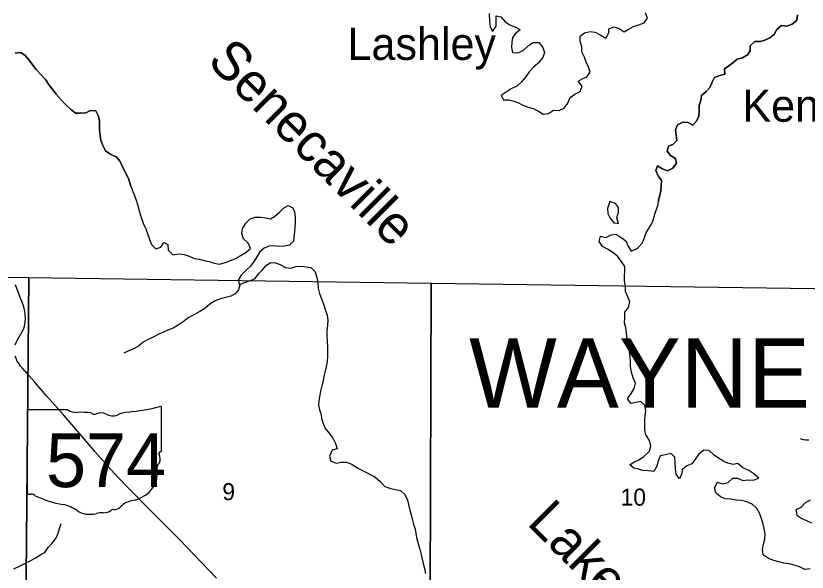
# Model space of a CAD drawing. Extents: x 0 to 191, y 0 to 55.
# Drawn here: x 144.524 to 145.495, y 22.998 to 23.68 of the extents above; entities that cross this region are included whole.
import ezdxf

# ---------------------------------------------------------------- set-up
doc = ezdxf.new("R2010")
doc.units = 0
for name, color, linetype in [('GM_X_Corporation', 7, 'Continuous'), ('GM_X_Major_Lake', 7, 'Continuous'), ('GM_X_Major_Lake_Text', 7, 'Continuous'), ('GM_X_Minor_River', 7, 'Continuous'), ('GM_X_Section_Text', 7, 'Continuous'), ('GM_X_State_Location', 7, 'Continuous'), ('GM_X_State_Route', 7, 'Continuous'), ('GM_X_State_Shield', 7, 'Continuous'), ('GM_X_Township_Road', 7, 'Continuous'), ('GM_X_Township_Text', 7, 'Continuous'), ('GM_X_Unincorporated_Text', 7, 'Continuous')]:
    doc.layers.add(name, color=color, linetype=linetype)

msp = doc.modelspace()

# ---------------------------------------------------------------- linework, layer by layer
at = {"layer": 'GM_X_Corporation'}
for points in [[(144.54037, 23.35908), (144.5357, 22.85387), (144.03613, 22.86315), (144.04141, 23.36476)], [(145.03385, 23.35238), (145.03203, 22.84664), (144.5357, 22.85387), (144.54037, 23.35908)], [(145.53282, 23.34555), (145.53082, 22.83943), (145.03203, 22.84664), (145.03385, 23.35238)]]:
    msp.add_lwpolyline(points, close=True, dxfattribs=at)
at = {"layer": 'GM_X_Major_Lake'}
for points in [[(145.1046, 23.68315), (145.10503, 23.67367), (145.10602, 23.66703), (145.1087, 23.66098), (145.11339, 23.66746), (145.11336, 23.67353), (145.11351, 23.68017), (145.119, 23.67906), (145.12434, 23.67284), (145.13004, 23.66927), (145.13687, 23.66628), (145.14294, 23.6631), (145.13748, 23.6587), (145.13354, 23.65355), (145.13262, 23.64786), (145.13228, 23.6414), (145.13346, 23.63515), (145.14008, 23.63463), (145.14631, 23.6377), (145.1529, 23.64362), (145.15893, 23.64745), (145.16575, 23.64731), (145.17051, 23.64146), (145.17244, 23.63521), (145.17059, 23.62894), (145.16476, 23.62208), (145.15911, 23.61711), (145.15366, 23.61138), (145.14916, 23.60472), (145.14446, 23.599), (145.13862, 23.59403), (145.13183, 23.59057), (145.1258, 23.58655), (145.11958, 23.58234), (145.12244, 23.57724), (145.12907, 23.5769), (145.13381, 23.57598), (145.13988, 23.57374), (145.14595, 23.57056), (145.15259, 23.56813), (145.15885, 23.56628), (145.16511, 23.56328), (145.17119, 23.55934), (145.17762, 23.56033), (145.18365, 23.56435), (145.19046, 23.56401), (145.19669, 23.56671), (145.2012, 23.57299), (145.204, 23.57984), (145.20984, 23.58386), (145.21625, 23.5875), (145.21868, 23.59378), (145.2141, 23.60001), (145.21957, 23.60346), (145.22447, 23.60538), (145.2286, 23.61091), (145.22667, 23.61735), (145.2238, 23.62321)], [(145.2238, 23.62321), (145.22149, 23.62945), (145.21842, 23.63607), (145.21858, 23.64252), (145.21627, 23.64877), (145.21642, 23.65503), (145.22169, 23.65942), (145.2285, 23.66098), (145.23456, 23.65988), (145.24082, 23.6567), (145.24766, 23.65276), (145.2516, 23.65923), (145.25138, 23.66397), (145.25799, 23.66667), (145.26405, 23.66462), (145.27051, 23.66068), (145.27655, 23.66413), (145.28183, 23.6672), (145.28825, 23.66914), (145.29486, 23.67164), (145.29899, 23.67717), (145.29668, 23.68361)], [(145.2874, 23.39603), (145.29286, 23.40175), (145.29509, 23.40821), (145.29695, 23.41335), (145.29957, 23.4181), (145.3037, 23.42477), (145.30575, 23.42952), (145.30798, 23.43693), (145.31188, 23.4489), (145.31242, 23.45384), (145.31372, 23.45897), (145.31519, 23.46523), (145.31572, 23.4715), (145.31606, 23.47814), (145.31187, 23.48399), (145.30899, 23.49042), (145.31123, 23.49631), (145.3173, 23.49256), (145.32356, 23.49013), (145.33017, 23.4934), (145.33467, 23.49931), (145.33313, 23.50518), (145.32705, 23.50874), (145.32304, 23.51403), (145.32452, 23.52029), (145.33019, 23.52241), (145.3347, 23.52737), (145.3339, 23.53382), (145.3333, 23.54026), (145.33591, 23.54654), (145.34214, 23.54961), (145.34876, 23.54927), (145.35465, 23.5459), (145.35916, 23.55086), (145.36177, 23.55713), (145.36212, 23.5632), (145.36246, 23.56984), (145.3645, 23.57649), (145.36522, 23.58238), (145.37106, 23.58735), (145.37538, 23.59212), (145.37837, 23.59858), (145.38118, 23.60448), (145.3876, 23.60699), (145.39364, 23.60873), (145.39342, 23.61518), (145.3985, 23.61863), (145.40359, 23.62264), (145.40886, 23.62704), (145.41529, 23.62878), (145.42151, 23.63224), (145.42489, 23.63719), (145.42485, 23.64345), (145.43069, 23.64861), (145.43731, 23.64865), (145.44279, 23.65039), (145.44902, 23.65309), (145.45411, 23.6571), (145.45748, 23.66338), (145.46312, 23.66835), (145.46994, 23.66725), (145.47636, 23.66976), (145.4822, 23.67435), (145.48292, 23.68118)], [(145.48292, 23.68118), (145.4822, 23.67435), (145.47636, 23.66976), (145.46994, 23.66725), (145.46312, 23.66835), (145.45748, 23.66338), (145.45411, 23.6571), (145.44902, 23.65309), (145.44279, 23.65039), (145.43731, 23.64865), (145.43069, 23.64861), (145.42485, 23.64345), (145.42489, 23.63719), (145.42151, 23.63224), (145.41529, 23.62878), (145.40886, 23.62704), (145.40359, 23.62264), (145.3985, 23.61863), (145.39342, 23.61518), (145.39364, 23.60873), (145.3876, 23.60699), (145.38118, 23.60448), (145.37837, 23.59858), (145.37538, 23.59212), (145.37106, 23.58735), (145.36522, 23.58238), (145.3645, 23.57649), (145.36246, 23.56984), (145.36212, 23.5632), (145.36177, 23.55713), (145.35916, 23.55086), (145.35465, 23.5459), (145.34876, 23.54927), (145.34214, 23.54961), (145.33591, 23.54654), (145.3333, 23.54026), (145.3339, 23.53382), (145.3347, 23.52737), (145.33019, 23.52241), (145.32452, 23.52029), (145.32304, 23.51403), (145.32705, 23.50874), (145.33313, 23.50518), (145.33467, 23.49931), (145.33017, 23.4934), (145.32356, 23.49013), (145.3173, 23.49256), (145.31123, 23.49631), (145.30899, 23.49042), (145.31187, 23.48399), (145.31606, 23.47814), (145.31572, 23.4715), (145.31519, 23.46523), (145.31372, 23.45897), (145.31242, 23.45384), (145.31224, 23.45219)], [(144.66622, 23.46937), (144.66468, 23.4736), (144.66256, 23.48061), (144.65567, 23.49422), (144.65222, 23.5014), (144.64726, 23.50706), (144.64081, 23.51024), (144.63454, 23.51476), (144.6309, 23.52099), (144.6286, 23.52724), (144.62761, 23.5333), (144.62682, 23.53974), (144.62679, 23.54448), (144.62694, 23.55074), (144.62558, 23.55718), (144.62251, 23.56342), (144.61589, 23.56414), (144.61022, 23.56126), (144.60379, 23.56084), (144.59755, 23.5608), (144.59127, 23.5655), (144.58518, 23.57134), (144.58004, 23.57718), (144.57375, 23.58397), (144.57013, 23.58888), (144.56517, 23.59492), (144.56078, 23.60191), (144.55544, 23.60794), (144.54935, 23.61416), (144.54019, 23.62624), (144.53543, 23.6319), (144.52992, 23.63509), (144.52349, 23.63429)], [(144.52349, 23.63429), (144.52992, 23.63509), (144.53543, 23.6319), (144.54019, 23.62624), (144.54935, 23.61416), (144.55544, 23.60794), (144.56078, 23.60191), (144.56517, 23.59492), (144.57013, 23.58888), (144.57375, 23.58397), (144.58004, 23.57718), (144.58518, 23.57134), (144.59127, 23.5655), (144.59755, 23.5608), (144.60379, 23.56084), (144.61022, 23.56126), (144.61589, 23.56414), (144.62251, 23.56342), (144.62558, 23.55718), (144.62694, 23.55074), (144.62679, 23.54448), (144.62682, 23.53974), (144.62761, 23.5333), (144.6286, 23.52724), (144.6309, 23.52099), (144.63454, 23.51476), (144.64081, 23.51024), (144.64726, 23.50706), (144.65222, 23.5014), (144.65567, 23.49422), (144.66256, 23.48061), (144.66468, 23.4736), (144.66757, 23.46566), (144.66988, 23.4596), (144.67238, 23.45279), (144.6745, 23.44598), (144.67605, 23.43992), (144.67798, 23.43291), (144.68067, 23.42591), (144.68374, 23.41892), (144.68586, 23.41305), (144.68836, 23.40586), (144.69105, 23.39943), (144.696, 23.39453), (144.70223, 23.39628), (144.70599, 23.40199), (144.71073, 23.39956), (144.71115, 23.39273), (144.71705, 23.38708)], [(144.71705, 23.38708), (144.72424, 23.38807), (144.73067, 23.38755), (144.73712, 23.3855), (144.74301, 23.38251), (144.74907, 23.3816), (144.75532, 23.38012), (144.76157, 23.37883), (144.76764, 23.37697), (144.77427, 23.37569), (144.78089, 23.37744), (144.78693, 23.37956), (144.79354, 23.38264), (144.80033, 23.38629), (144.80674, 23.39031), (144.8122, 23.39471), (144.80913, 23.40151), (144.80361, 23.4066), (144.8015, 23.41304), (144.80222, 23.4193), (144.80653, 23.42577), (144.8118, 23.43131), (144.81803, 23.43324), (144.82447, 23.4331), (144.83053, 23.43238), (144.83659, 23.43128), (144.84149, 23.43396), (144.84771, 23.4395), (144.85241, 23.44446), (144.85844, 23.44773), (144.86395, 23.44473), (144.86606, 23.43962), (144.86705, 23.43356), (144.86689, 23.4273), (144.86655, 23.42104), (144.86602, 23.41478), (144.86511, 23.40851), (144.86495, 23.40377), (144.85987, 23.3988), (144.85401, 23.39782), (144.84739, 23.3974), (144.84095, 23.39812), (144.83471, 23.39751), (144.82885, 23.39519), (144.82339, 23.39061), (144.82002, 23.38471), (144.81683, 23.37937), (144.81214, 23.37328), (144.8063, 23.36774), (144.80066, 23.3622), (144.79691, 23.35592), (144.79883, 23.35062), (144.80525, 23.35313), (144.81205, 23.35564), (144.81791, 23.35814), (144.82185, 23.36386), (144.82693, 23.36863), (144.83125, 23.37378), (144.83653, 23.3776), (144.84278, 23.37708), (144.84847, 23.37503), (144.85511, 23.37147), (144.86174, 23.37056), (144.86759, 23.37287), (144.87421, 23.37329), (144.88028, 23.37238), (144.88596, 23.37147), (144.89129, 23.3662), (144.8936, 23.35919), (144.89459, 23.35256), (144.89519, 23.34612), (144.89655, 23.33968), (144.89924, 23.33306), (144.90174, 23.32644), (144.90367, 23.31981), (144.90617, 23.313), (144.90696, 23.30713), (144.90662, 23.30068), (144.90591, 23.29384), (144.90576, 23.28721), (144.90617, 23.28095), (144.9064, 23.27431), (144.90662, 23.26863), (144.90647, 23.26275), (144.90594, 23.25611), (144.90484, 23.24965), (144.90337, 23.24262), (144.90226, 23.23788), (144.90116, 23.23237), (144.89968, 23.22629), (144.89783, 23.21983), (144.89673, 23.213), (144.896, 23.20787), (144.89565, 23.20313), (144.89682, 23.19707), (144.89875, 23.1912), (144.89916, 23.18646), (144.90109, 23.18022), (144.90358, 23.17417), (144.90854, 23.16832), (144.91293, 23.16209)], [(145.25278, 23.45228), (145.2498, 23.44373), (145.25021, 23.43766), (145.25327, 23.43199), (145.25747, 23.42633), (145.2587, 23.42618)], [(145.2587, 23.42618), (145.26353, 23.4256), (145.26122, 23.43261), (145.26327, 23.43926), (145.26323, 23.44513), (145.25961, 23.45004), (145.25278, 23.45228)], [(145.38091, 23.10154), (145.38484, 23.1082), (145.39129, 23.10635), (145.39772, 23.10771), (145.40336, 23.11306), (145.40942, 23.11329), (145.41568, 23.11048), (145.42192, 23.11109), (145.42836, 23.11056), (145.43534, 23.11326), (145.42926, 23.11853), (145.42299, 23.12248), (145.41578, 23.12603), (145.4095, 23.13111), (145.40383, 23.12994), (145.39739, 23.13142), (145.39264, 23.13347), (145.38619, 23.1376), (145.38067, 23.14155), (145.37459, 23.14701), (145.36815, 23.14735), (145.36156, 23.14238), (145.35311, 23.13095), (145.34707, 23.12825), (145.34142, 23.12347), (145.34107, 23.11873), (145.33808, 23.11245), (145.33407, 23.11812), (145.33346, 23.12475), (145.33304, 23.13158), (145.33262, 23.13878), (145.32786, 23.14349), (145.32106, 23.14174), (145.31445, 23.14056), (145.31221, 23.1341), (145.31035, 23.12802), (145.3068, 23.12136), (145.29998, 23.12226), (145.29335, 23.12279), (145.28672, 23.12446), (145.28198, 23.12556), (145.27723, 23.12951), (145.28269, 23.13315), (145.2876, 23.13508), (145.29439, 23.13986), (145.30135, 23.14636), (145.30321, 23.15263), (145.30128, 23.15944), (145.29707, 23.16624), (145.29553, 23.17192), (145.29568, 23.17875), (145.29583, 23.18501), (145.29618, 23.18975), (145.29671, 23.1962), (145.29554, 23.20264), (145.29078, 23.20735), (145.28454, 23.20599), (145.27906, 23.20462), (145.27449, 23.21028), (145.2788, 23.21695), (145.28274, 23.22323), (145.2844, 23.2295), (145.28115, 23.23631), (145.27921, 23.24331), (145.27823, 23.24994), (145.278, 23.25582), (145.27778, 23.26246), (145.27698, 23.26871), (145.27733, 23.27364), (145.27938, 23.2801), (145.27386, 23.28424), (145.27326, 23.29106), (145.27227, 23.2975), (145.27091, 23.30375), (145.27106, 23.3102), (145.27102, 23.31665), (145.27572, 23.32256), (145.27719, 23.3294), (145.2747, 23.33564), (145.27201, 23.34207), (145.27178, 23.34852), (145.2708, 23.35496), (145.27076, 23.3616), (145.27111, 23.36634), (145.27107, 23.3726), (145.26668, 23.37921), (145.2621, 23.38524), (145.2564, 23.38976), (145.24994, 23.39389), (145.24368, 23.39708), (145.23948, 23.4035), (145.24133, 23.40996), (145.24778, 23.40848), (145.25419, 23.41137), (145.26043, 23.41235), (145.26651, 23.40841), (145.27221, 23.40408), (145.27528, 23.39766), (145.2791, 23.39161), (145.28533, 23.39431), (145.2874, 23.39603)], [(144.91293, 23.16209), (144.91656, 23.15585), (144.91849, 23.14923), (144.91244, 23.14748), (144.90889, 23.14025), (144.91082, 23.13401), (144.91746, 23.13177), (144.92351, 23.13276), (144.92994, 23.13261), (144.9362, 23.13019), (144.94285, 23.12587), (144.94778, 23.12343), (144.95424, 23.12006), (144.95974, 23.11725), (144.96468, 23.11463), (144.97133, 23.10917), (144.97705, 23.10314), (144.98425, 23.10053), (144.98937, 23.09924), (144.996, 23.09795), (145.00133, 23.09324), (145.00478, 23.08606), (145.00576, 23.08076), (145.00711, 23.07545), (145.01021, 23.06334), (145.01214, 23.0569), (145.01388, 23.05046), (145.01504, 23.04554), (145.01622, 23.03891), (145.01815, 23.03153), (145.01989, 23.02623), (145.02125, 23.0196), (145.02261, 23.01373), (145.02416, 23.0071), (145.0259, 23.00086), (145.02688, 22.99612)], [(145.49844, 23.00216), (145.49182, 23.00136), (145.48537, 23.00454), (145.47892, 23.00639), (145.47248, 23.00806), (145.46604, 23.00897), (145.45998, 23.01045), (145.45391, 23.01211), (145.44746, 23.01473), (145.44081, 23.01905), (145.43983, 23.02587), (145.4413, 23.03213), (145.44297, 23.03821), (145.44312, 23.04504), (145.44214, 23.05129), (145.44078, 23.05697), (145.43866, 23.06322), (145.43655, 23.06927), (145.4331, 23.07608), (145.4272, 23.08135), (145.42056, 23.08434), (145.41412, 23.08601), (145.40749, 23.08635), (145.40105, 23.08725), (145.39405, 23.08797), (145.38836, 23.09021), (145.38265, 23.09529), (145.38091, 23.10154)], [(145.49833, 23.08617), (145.49173, 23.08252), (145.48684, 23.07737), (145.48061, 23.0743), (145.48216, 23.06767), (145.48805, 23.06372), (145.49374, 23.06129), (145.50001, 23.05849)]]:
    msp.add_lwpolyline(points, dxfattribs=at)
at = {"layer": 'GM_X_Minor_River'}
for points in [[(144.79952, 23.35089), (144.79722, 23.34419), (144.79327, 23.33924), (144.78817, 23.33656), (144.78155, 23.33481), (144.77531, 23.33326), (144.7687, 23.33056), (144.76247, 23.32673), (144.75606, 23.32139), (144.74983, 23.31737), (144.74342, 23.31392), (144.73567, 23.30989), (144.72945, 23.30473), (144.7236, 23.3009), (144.71718, 23.29726), (144.71057, 23.29457), (144.70547, 23.29226), (144.69886, 23.28919), (144.69282, 23.28593), (144.68678, 23.28305), (144.68073, 23.27979), (144.6747, 23.2752), (144.6679, 23.27137), (144.66299, 23.26926), (144.65676, 23.26637)], [(144.52185, 23.00197), (144.52959, 23.00562), (144.53639, 23.00889), (144.5413, 23.01138), (144.54904, 23.01541), (144.55433, 23.01923), (144.5598, 23.02211), (144.56412, 23.02821), (144.56845, 23.03316), (144.57353, 23.03926), (144.57615, 23.04591), (144.57819, 23.05275), (144.58006, 23.05751)]]:
    msp.add_lwpolyline(points, dxfattribs=at)
at = {"layer": 'GM_X_State_Route'}
for points in [[(144.52352, 23.27687), (144.52493, 23.27965), (144.52633, 23.28286), (144.53244, 23.29359), (144.53413, 23.29729), (144.53489, 23.29942), (144.53541, 23.30204), (144.53582, 23.30497), (144.5361, 23.30864), (144.53598, 23.3135), (144.53542, 23.31766), (144.5346, 23.32149), (144.53325, 23.3257), (144.53182, 23.32995), (144.5295, 23.33596), (144.52412, 23.35046)], [(144.77032, 22.9906), (144.76156, 22.99997), (144.73399, 23.02855), (144.72459, 23.03842), (144.68749, 23.07557), (144.66311, 23.10047), (144.6504, 23.11371), (144.64095, 23.12372), (144.62126, 23.14594), (144.6082, 23.16153), (144.58288, 23.19075), (144.56214, 23.21414), (144.54727, 23.23122), (144.53783, 23.24187), (144.53244, 23.24794), (144.53027, 23.25055), (144.52788, 23.254), (144.52609, 23.25686), (144.52464, 23.25978), (144.52376, 23.26297)]]:
    msp.add_lwpolyline(points, dxfattribs=at)
at = {"layer": 'GM_X_State_Shield'}
for p, q in [((144.53821, 23.19522), (144.53821, 23.09516)), ((144.58809, 23.19694), (144.53983, 23.19694)), ((144.703, 23.14708), (144.703, 23.19942)), ((144.70299, 23.14709), (144.703, 23.14708))]:
    msp.add_line(p, q, dxfattribs=at)
for centre, major_axis, start_param, end_param in [((144.6443, 23.33336), (0.17476, 0), 4.814394, 5.042369), ((144.70117, 23.19964), (0.00183, 0), 6.141152, 7.989035), ((144.5401, 23.19543), (0.00191, 0), 1.712693, 3.28349), ((144.59959, 23.20856), (0.01852, 0), 4.042523, 4.731795), ((144.60572, 23.14077), (0.06648, 0), 1.404758, 1.657858), ((144.62082, 23.19595), (0.00534, 0), 3.836095, 5.185415), ((144.62866, 23.18439), (0.01111, 0), 0.950623, 2.079405), ((144.64299, 23.20025), (0.01336, 0), 4.081561, 5.145723), ((144.66659, 23.16638), (0.03516, 0), 1.699011, 2.107814), ((144.70258, 23.14323), (0.00284, 0), 1.883978, 3.671073), ((144.70104, 23.14688), (0.00196, 0), 5.05454, 6.418171), ((144.68452, 23.13662), (0.01704, 0), 5.934695, 6.695948), ((144.65409, 23.11851), (0.04371, 0), 5.101752, 6.440018), ((144.70957, 23.12517), (0.0124, 0), 2.387724, 3.262537), ((144.54011, 23.09494), (0.00193, 0), 3.00124, 4.508301), ((144.54041, 23.10518), (0.0147, 0), 4.665946, 4.897461), ((144.54341, 23.08939), (0.0053, 0), 0.519207, 1.627899), ((144.61033, 23.17929), (0.1262, 0), 4.195997, 4.488961), ((144.67252, 23.06707), (0.02394, 0), 1.647645, 2.488434), ((144.5727, 23.05021), (0.03949, 0), 0.823519, 1.323587), ((144.64379, 23.07171), (0.00376, 0), 1.147584, 2.315152), ((144.64219, 23.08546), (0.01412, 0), 4.937069, 5.64225), ((144.61541, 23.08889), (0.02506, 0), 4.026481, 4.996735), ((144.62989, 23.05429), (0.02059, 0), 1.495662, 1.94098), ((144.63172, 23.0814), (0.01335, 0), 4.691044, 5.507374)]:
    msp.add_ellipse(centre, major_axis=major_axis, ratio=0.8, start_param=start_param, end_param=end_param, dxfattribs=at)
at = {"layer": 'GM_X_Township_Road'}
msp.add_lwpolyline([(145.49684, 23.15964), (145.49327, 23.15986), (145.49003, 23.16024), (145.48652, 23.16134)], dxfattribs=at)

# ---------------------------------------------------------------- texts
at = {"layer": 'GM_X_Major_Lake_Text'}
for s, height, rotation, p in [('Senecaville', 0.0473484, 315.00209, (144.75768, 23.62309)), ('Lake', 0.047343, 315.00121, (145.14987, 23.05718))]:
    msp.add_text(s, height=height, rotation=rotation, dxfattribs=at).set_placement(p)
at = {"layer": 'GM_X_Section_Text'}
for s, height, p in [('9', 0.02093, (144.77761, 23.08612)), ('10', 0.020928, (145.26595, 23.07945))]:
    msp.add_text(s, height=height, rotation=0.00001, dxfattribs=at).set_placement(p)
at = {"layer": 'GM_X_State_Location'}
for s in ['s', 'r']:
    msp.add_text(s, height=0.0000947, dxfattribs=at).set_placement((144.61875, 23.13854))
msp.add_text('574', height=0.0000947, rotation=0.00001, dxfattribs=at).set_placement((144.58532, 23.13165))
at = {"layer": 'GM_X_State_Shield'}
msp.add_text('574', height=0.065918, dxfattribs=at).set_placement((144.56147, 23.10221))
at = {"layer": 'GM_X_Township_Text'}
msp.add_text('WAYNE', height=0.085227, rotation=0.00001, dxfattribs=at).set_placement((145.08017, 23.19956))
at = {"layer": 'GM_X_Unincorporated_Text'}
for s, height, p in [('Lashley', 0.039489, (144.93116, 23.62607)), ('Kennonsburg', 0.0394886, (145.41532, 23.55023))]:
    msp.add_text(s, height=height, rotation=0.00001, dxfattribs=at).set_placement(p)

doc.saveas('drawing.dxf')
